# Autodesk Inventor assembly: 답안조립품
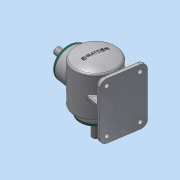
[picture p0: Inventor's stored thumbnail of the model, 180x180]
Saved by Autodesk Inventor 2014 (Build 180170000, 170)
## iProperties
Created: 2016-09
Part Number: 답안조립품
Document SubType Name: Assembly
Designer: 402-003
Author: 402-003
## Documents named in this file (14)
- C:\Users\402-003\Desktop\460907V1009\답안조립품.iam
- C:\Users\402-003\Desktop\460907V1009\본체.ipt
- C:\Users\402-003\Desktop\460907V1009\M4.ipt
- C:\Users\402-003\Desktop\460907V1009\메인 베벨기어.ipt
- C:\Users\402-003\Desktop\460907V1009\메인 축.ipt
- 메인 축.ipt
- C:\Users\402-003\Desktop\460907V1009\베어링 6203.ipt
- C:\Users\402-003\Desktop\460907V1009\서브 베벨기어.ipt
- C:\Users\402-003\Desktop\460907V1009\서브 축.ipt
- 서브 축.ipt
- C:\Users\402-003\Desktop\460907V1009\오일실 17 32 8.ipt
- C:\Users\402-003\Desktop\460907V1009\커버.ipt
- C:\Users\402-003\Desktop\460907V1009\키 4x4.ipt
- C:\Users\402-003\Desktop\460907V1009\키 5x5.ipt
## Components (8 placed, 1 different names)
1. M4:2 — 각도:1
2. M4:3
3. M4:4
4. M4:5
5. M4:1 — 각도:2
6. M4:6
7. M4:7
8. M4:8
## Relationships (2: Angle 2)
- 각도:1 [Angle]: M4:2
- 각도:2 [Angle]: M4:1
